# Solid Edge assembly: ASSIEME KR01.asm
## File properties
Subject: ASSIEME KR01
Author: f_grande
Template: Normal.asm
Last saved by: f_grande
Revision: 53
Application: Solid Edge
Tipo di contenuto documento: 1
Document Number: KR0120
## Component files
ASSIEME BASE KR01.asm
ASSIEME TOP KR01.asm
dado M10 normale.par
COPERTURA LATERALE.psm
9351021390.par
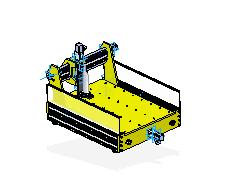
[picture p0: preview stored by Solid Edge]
